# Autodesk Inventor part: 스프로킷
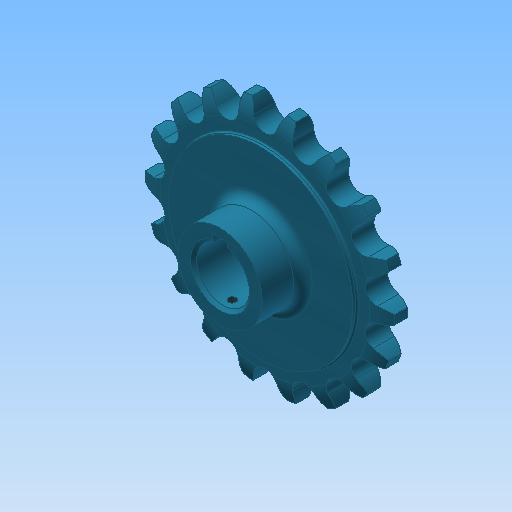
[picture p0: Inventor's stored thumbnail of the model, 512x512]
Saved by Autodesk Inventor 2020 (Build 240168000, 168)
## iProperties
Created: 2016-03
Part Number: 스프로킷
Material: 강철, 탄소
Document SubType Name: Modeling
Designer: mduedu
Density: 7.87 g/cm^3
Mass: 301.818 g
Surface Area: 124.882 cm^2
Volume: 38.3505 cm^3
Appearance: 터키옥색
Author: mduedu
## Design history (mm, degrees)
sketch "스케치1"
  geometry: L1 (0, 5)-(29.5, 5); L2 (29.5, 5)-(29.5, 4.1); L3 (30, 3.6)-(33.625, 3.6); L4 (40, 2)-(40, 0); L5 (40, 0)-(0, 0); L6 (0, 0)-(0, 5); L7 (0, -5)-(29.5, -5); L8 (29.5, -5)-(29.5, -4.1); L9 (30, -3.6)-(33.625, -3.6); L10 (40, -2)-(40, 0); L11 (0, 0)-(0, -5); A1 r 13.5 centre (33.625, -9.9) between (40, 2) and (33.625, 3.6); A2 r 13.5 centre (33.625, 9.9) between (33.625, -3.6) and (40, -2); A3 r 0.5 centre (30, 4.1) between (29.5, 4.1) and (30, 3.6); A4 r 0.5 centre (30, -4.1) between (30, -3.6) and (29.5, -4.1); 2 further points
  constraints: 22 end point, 8 point on circle, 6 symmetric about line, 5 tangent, 4 centre point, 4 parallel, 4 point on line, 1 equal radius, 1 horizontal, 1 perpendicular, 1 other
  dimensions: "d0" = 80 diameter of L4 L6; "d2" = 59 diameter of L2 L6; "d3" = 1.6 vertical distance of L4.start L3.end; "d4" = 3.6 distance from line of L4.end L3; "d5" = 5 distance between parallel lines of L5 L1; "d6" = 13.5 radius of A1; "d15" = 0.5 radius of A3
revolve "회전1" sketch "스케치1" stored, may be unused: angle "d7" = 90 deg
sketch "스케치2" dims "d8" = 65.2, "d11" = 80
  geometry: L1 (0, 0)-(0, 32.6); A1 r 36.57 centre (0, 0) between (-16.231, 32.771) and (0, 36.57); A2 r 3.97 centre (0, 36.57) between (-3.866, 35.665) and (0, 32.6); A3 r 12.7 centre (-16.231, 32.771) between (-3.866, 35.665) and (-5.534, 39.615); A4 r 12.7 centre (16.231, 32.771) between (5.534, 39.615) and (3.866, 35.665); A5 r 3.97 centre (0, 36.57) between (0, 32.6) and (3.866, 35.665); A6 r 40 centre (0, 0) between (5.534, 39.615) and (-5.534, 39.615); 2 further points
  constraints: 12 point on circle, 6 centre point, 4 coincident, 3 symmetric about line, 2 end point, 1 point on line, 1 tangent, 1 vertical, 1 vertical alignment, 7 other
  dimensions: "d10" = 73.14 diameter of A1; "d12" = 12.7 radius of A3
extrude "돌출1" cut sketch "스케치2" extent not by distance; stored distance "d13" = 10; taper "d14" = 0 deg
sketch "스케치3"
  geometry: C1 r 13.5 at (0, 0); 1 further point
  constraints: 1 centre point, 1 coincident
  dimensions: "d19" = 27 diameter of C1
extrude "돌출2" join sketch "스케치3" distance "d20" = 13; taper "d21" = 0 deg
fillet "모깎기1" dims "d22" = 3
sketch "스케치4"
  geometry: L1 (-2.5, 0)-(2.5, 0); L2 (2.5, 0)-(2.5, 10.8); L3 (2.5, 10.8)-(-2.5, 10.8); L4 (-2.5, 10.8)-(-2.5, 0); C1 r 8.5 at (0, 0); 2 further points
  constraints: 8 end point, 2 coincident, 2 parallel, 1 centre point, 1 horizontal, 1 midpoint, 1 perpendicular
  dimensions: "d23" = 17 diameter of C1; "d25" = 5 distance of L2.end L3.end; "d26" = 10.8 distance of L1.end L2.end
extrude "돌출3" cut sketch "스케치4" extent not by distance; stored distance "d27" = 8; taper "d28" = 0 deg
chamfer "모따기1" distance "d29" = 1; stored, may be unused: second distance "d30" = 2, angle "d31" = 45 deg
node "작업 평면1"
sketch "스케치5"
  geometry: L1 (13.5, 13)-(-13.5, 13) reference; 2 further points
  constraints: 1 vertical alignment
  dimensions: "d32" = 4 distance from line of point (0, 9) L1
hole "구멍1" sketch "스케치5" at (0, 9) diameter "d33" = 2.459; stored, may be unused: countersink angle "d37" = 90 deg, drill point angle "d39" = 118 deg; dims "d34" = 6, "d35" = 4, "d36" = 2, "d38" = 8
node "솔리드1"
pattern_circular "원형 패턴1" dims angle "d17" = 360 deg
